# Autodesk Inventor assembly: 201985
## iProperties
Created: 2007-12
Part Number: 201985
Document SubType Name: Assembly
Designer: MM
Mass: 109.117 g
Surface Area: 82.6289 cm^2
Volume: 17.355 cm^3
Density: 6.28739 g/cm^3
Description: BALL SCREW SHAFT ASSEMBLY
Component Category: Lower Component
Author: MM
